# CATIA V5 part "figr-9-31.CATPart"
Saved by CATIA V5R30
Part number: Part1
Bounding box of the stored display mesh (mm): x -60 to 60, y -41.231 to 41.231, z -41.231 to 41.231
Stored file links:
  D:\PROJECTS\CATIA V56R 2020\Resources\Parts File\c09_catia_v5_6r2020_prt\figr-9-31.CATPart
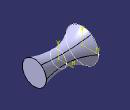
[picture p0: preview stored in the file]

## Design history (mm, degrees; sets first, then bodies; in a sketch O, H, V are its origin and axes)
Body1 (main body)
  Sketch1 on yz-plane, origin (0, 0, 0), H (0, 1, 0), V (0, 0, 1)
    circle A1 centre (0, 0) radius 20
  Plane1: type Offset, RefPlane yz-plane, Offset 60
  Plane2: type Offset, RefPlane yz-plane, Offset -60
  Sketch2 on Plane1, origin (60, 0, 0), H (0, 1, 0), V (0, 0, 1)
    circle A1 centre (0, 0) radius 30
  Sketch3 on Plane2, origin (-60, 0, 0), H (0, 1, 0), V (0, 0, 1)
    circle A1 centre (0, 0) radius 41.2311
  Loft1: solid, Sections (Sketch2; Sketch1; Sketch3)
